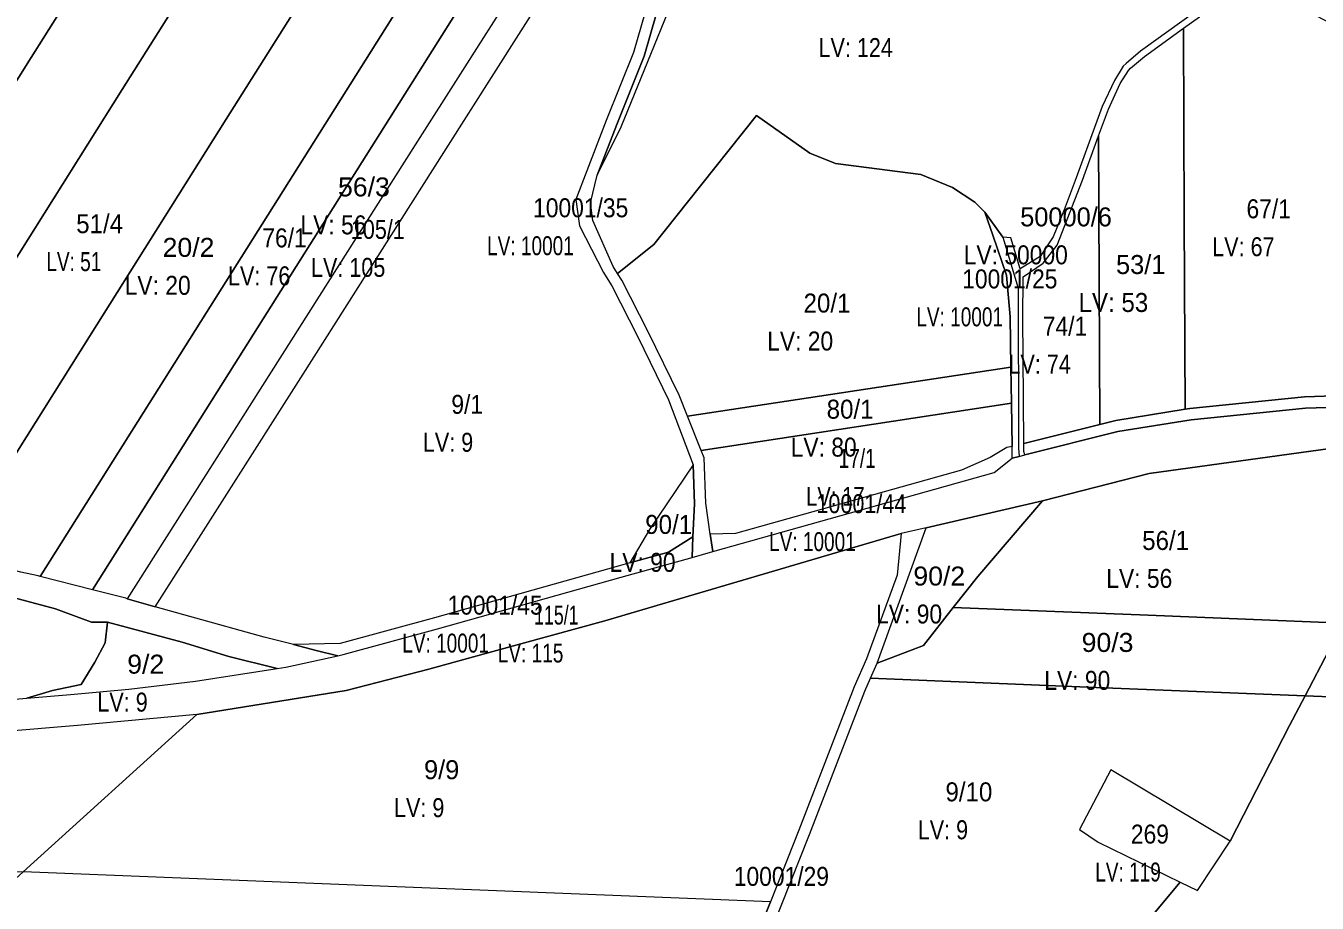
# Model space of a CAD drawing. Extents: x -713758 to -711119, y -1123067 to -1120789.
# Drawn here: x -712228 to -711548, y -1121714 to -1121252 of the extents above; entities that cross this region are included whole.
import ezdxf
from ezdxf.enums import TextEntityAlignment as Align

# ---------------------------------------------------------------- set-up
doc = ezdxf.new("R2010")
doc.units = 0
doc.header["$LTSCALE"] = 4
doc.layers.add('10', color=7, linetype='Continuous', lineweight=13)
doc.layers.add('11', color=7, linetype='Continuous')
doc.layers.add('13', color=7, linetype='Continuous')

msp = doc.modelspace()

# ---------------------------------------------------------------- linework, layer by layer
at = {"layer": '10'}
for points in [[(-712423.44, -1121490.64), (-712347.85, -1121370.61), (-712272.26, -1121250.57), (-712196.67, -1121130.54), (-712185, -1121136.71), (-712169.32, -1121143.39), (-712151.71, -1121151.12), (-712225.62, -1121268.49), (-712299.53, -1121385.85), (-712373.44, -1121503.22), (-712411.12, -1121493.7)], [(-712373.44, -1121503.22), (-712299.53, -1121385.85), (-712225.62, -1121268.49), (-712151.71, -1121151.12), (-712121.32, -1121164.46), (-712105.15, -1121170.27), (-712177.71, -1121285.5), (-712250.27, -1121400.74), (-712322.84, -1121515.97), (-712342.53, -1121511.25), (-712369.84, -1121504.13)], [(-712322.84, -1121515.97), (-712250.27, -1121400.74), (-712177.71, -1121285.5), (-712105.15, -1121170.27), (-712076.52, -1121180.56), (-712064.5, -1121183.42), (-712050.6, -1121186.42), (-712122.79, -1121301.06), (-712194.99, -1121415.7), (-712267.18, -1121530.34), (-712312.23, -1121518.51)], [(-711927.19, -1121330.54), (-711914.62, -1121305.06), (-711890.03, -1121244.84), (-711869.08, -1121184.54), (-711877.22, -1121181.83), (-711901.86, -1121183.16), (-711916.62, -1121185.66), (-711913.13, -1121194.47), (-711902.89, -1121203.34), (-711894.77, -1121216.03), (-711893.42, -1121230.17), (-711896.16, -1121245.95), (-711902.41, -1121267.94), (-711916.98, -1121303.92)], [(-712267.18, -1121530.34), (-712194.99, -1121415.7), (-712122.79, -1121301.06), (-712050.6, -1121186.42), (-712045.54, -1121187.51), (-712026.93, -1121189.41), (-712000.06, -1121191.51), (-712073.66, -1121308.39), (-712147.26, -1121425.26), (-712220.86, -1121542.14), (-712221.92, -1121541.87), (-712231.21, -1121539.78)], [(-712220.86, -1121542.14), (-712147.26, -1121425.26), (-712073.66, -1121308.39), (-712000.06, -1121191.51), (-711991.96, -1121192.14), (-711969.33, -1121193.53), (-712043.98, -1121312.07), (-712118.64, -1121430.62), (-712193.29, -1121549.17)], [(-712193.29, -1121549.17), (-712118.64, -1121430.62), (-712043.98, -1121312.07), (-711969.33, -1121193.53), (-711947.16, -1121194.88), (-712023.15, -1121314.53), (-712099.14, -1121434.18), (-712175.12, -1121553.83), (-712175.81, -1121553.63)], [(-712175.12, -1121553.83), (-712160.23, -1121558.04), (-712083.56, -1121437.33), (-712006.9, -1121316.63), (-711930.24, -1121195.92), (-711947.16, -1121194.88), (-712023.15, -1121314.53), (-712099.14, -1121434.18)], [(-711618.17, -1121253.17), (-711609.76, -1121247.05), (-711603.45, -1121237.97), (-711602.78, -1121237.53), (-711594.67, -1121232.25), (-711577.63, -1121234.79), (-711563.68, -1121238.26), (-711544.69, -1121248.43), (-711525.27, -1121257.57), (-711523.81, -1121258.22), (-711523.01, -1121446.38), (-711554.24, -1121447.4), (-711614.82, -1121453.59), (-711617.32, -1121453.99), (-711617.74, -1121353.58)], [(-711662.88, -1121309.79), (-711657.75, -1121295.8), (-711651.46, -1121282.29), (-711647.11, -1121275.38), (-711646.02, -1121274.27), (-711638.61, -1121268.05), (-711618.17, -1121253.17), (-711617.74, -1121353.58), (-711617.32, -1121453.99), (-711653.87, -1121459.84), (-711662.24, -1121461.94)], [(-711916.53, -1121382.42), (-711897.38, -1121367.21), (-711879.72, -1121344.83), (-711843.34, -1121299.08), (-711815.1, -1121319.03), (-711801.61, -1121324.49), (-711756.69, -1121330.16), (-711739.96, -1121337.15), (-711728.17, -1121344.84), (-711722.83, -1121350.06), (-711718.64, -1121362.29), (-711711.51, -1121383.25), (-711709.53, -1121405.21), (-711709.15, -1121431.75), (-711879.64, -1121457.61), (-711884.11, -1121446.52), (-711900.43, -1121413.1), (-711914.27, -1121385.94)], [(-711702.78, -1121406.41), (-711702.63, -1121384.21), (-711692.16, -1121376.91), (-711684.76, -1121367.47), (-711671.45, -1121333.16), (-711662.88, -1121309.79), (-711662.24, -1121461.94), (-711702.26, -1121471.99), (-711702.67, -1121425.96)], [(-711722.83, -1121350.06), (-711713.32, -1121363.32), (-711705.36, -1121390.09), (-711705.36, -1121405.64), (-711705.06, -1121455.16), (-711705.15, -1121474.49), (-711704.85, -1121478.82), (-711708.45, -1121479.72), (-711708.54, -1121473.56), (-711708.87, -1121450.84), (-711709.15, -1121431.75), (-711709.53, -1121405.21), (-711711.51, -1121383.25), (-711718.64, -1121362.29)], [(-711879.64, -1121457.61), (-711709.15, -1121431.75), (-711708.87, -1121450.84), (-711872.37, -1121475.64)], [(-711872.37, -1121475.64), (-711708.87, -1121450.84), (-711708.54, -1121473.56), (-711711.19, -1121474.22), (-711719.98, -1121479.48), (-711735.24, -1121486.02), (-711854.28, -1121519.39), (-711867.64, -1121519.88), (-711870.02, -1121503.4), (-711870.8, -1121479.52)], [(-711867.64, -1121519.88), (-711866.32, -1121529), (-711717.95, -1121487.4), (-711708.45, -1121479.72), (-711708.54, -1121473.56), (-711711.19, -1121474.22), (-711719.98, -1121479.48), (-711735.24, -1121486.02), (-711854.28, -1121519.39)], [(-711739.48, -1121558.47), (-711726.6, -1121542.17), (-711692.52, -1121502.18), (-711636.21, -1121487.78), (-711535.72, -1121473.88), (-711490.84, -1121475.25), (-711507.4, -1121513.57), (-711534.18, -1121566.68), (-711636.83, -1121562.58)], [(-711910.02, -1121535.02), (-711889.72, -1121529.33), (-711876.74, -1121521.16), (-711876.01, -1121503.92), (-711876.68, -1121483.2), (-711899.75, -1121517.45)], [(-711779.66, -1121587.75), (-711761.86, -1121538.83), (-711753.72, -1121516.45), (-711692.52, -1121502.18), (-711726.6, -1121542.17), (-711739.48, -1121558.47), (-711755.26, -1121578.43)], [(-712229.88, -1121697.85), (-712138.38, -1121614.8), (-712059.59, -1121602.17), (-712016.1, -1121591.07), (-711982.28, -1121581.75), (-711923.15, -1121565.46), (-711766.99, -1121519.55), (-711769.17, -1121541.36), (-711785.23, -1121585.51), (-711791.73, -1121600.27), (-711820.89, -1121675.91), (-711835.92, -1121713.6), (-712032.9, -1121705.73)], [(-712087.41, -1121578.03), (-712075.42, -1121581.12), (-712063.93, -1121583.89), (-712061.14, -1121583.28), (-712011.52, -1121569.7), (-711914.59, -1121542.53), (-711877.21, -1121532.05), (-711876.74, -1121521.16), (-711889.72, -1121529.33), (-711910.02, -1121535.02), (-711916.2, -1121536.75), (-712013.08, -1121563.91), (-712062.72, -1121577.49)], [(-711783.2, -1121595.79), (-711779.66, -1121587.75), (-711755.26, -1121578.43), (-711739.48, -1121558.47), (-711636.83, -1121562.58), (-711534.18, -1121566.68), (-711541.43, -1121581.06), (-711553.99, -1121604.99), (-711668.6, -1121600.39)], [(-712228.02, -1121606.32), (-712204.87, -1121604.37), (-712174.24, -1121601.59), (-712139, -1121597.34), (-712095.99, -1121590.61), (-712121.43, -1121584.31), (-712146.04, -1121576.83), (-712185.46, -1121566.18), (-712186.71, -1121577.16), (-712192.08, -1121587.24), (-712199.33, -1121599.14), (-712214.41, -1121602.18)], [(-711553.99, -1121604.99), (-711541.43, -1121581.06), (-711534.18, -1121566.68), (-711412.4, -1121571.55), (-711290.62, -1121576.42), (-711308.45, -1121614.84), (-711431.22, -1121609.91)], [(-711835.08, -1121727.68), (-711815.31, -1121678.11), (-711786.19, -1121602.57), (-711783.2, -1121595.79), (-711668.6, -1121600.39), (-711553.99, -1121604.99), (-711562.27, -1121620.75), (-711593.45, -1121681.64), (-711656.45, -1121644), (-711672.97, -1121675.46), (-711663.14, -1121682.15), (-711619.93, -1121703.21), (-711643.78, -1121731.83), (-711646.68, -1121735.31)], [(-711646.68, -1121735.31), (-711643.78, -1121731.83), (-711619.93, -1121703.21), (-711610.76, -1121707.68), (-711593.45, -1121681.64), (-711562.27, -1121620.75), (-711553.99, -1121604.99), (-711431.22, -1121609.91), (-711308.45, -1121614.84), (-711315.94, -1121630.99), (-711342.08, -1121687.09), (-711372.92, -1121746.38), (-711509.8, -1121740.84)], [(-712310.25, -1121694.64), (-712229.88, -1121697.85), (-712138.38, -1121614.8), (-712201.33, -1121620.73), (-712241.17, -1121624.1), (-712284.89, -1121666.46)], [(-711672.97, -1121675.46), (-711663.14, -1121682.15), (-711619.93, -1121703.21), (-711610.76, -1121707.68), (-711593.45, -1121681.64), (-711656.45, -1121644)], [(-712345.4, -1121802.72), (-712182.69, -1121809.23), (-712019.97, -1121815.74), (-711857.26, -1121822.25), (-711854.58, -1121793.79), (-711851.16, -1121773.83), (-711848.33, -1121765.03), (-711850.53, -1121760.95), (-711852.87, -1121751.59), (-711845.69, -1121738.11), (-711835.92, -1121713.6), (-712032.9, -1121705.73), (-712229.88, -1121697.85)]]:
    msp.add_lwpolyline(points, close=True, dxfattribs=at)
for points in [[(-711902.02, -1121244.62), (-711908.09, -1121265.99), (-711922.57, -1121301.74), (-711932.79, -1121328.39), (-711938.51, -1121343.33), (-711936.63, -1121357.22), (-711923.91, -1121381.87), (-711921.62, -1121385.61), (-711919.48, -1121388.93), (-711905.79, -1121415.8), (-711889.59, -1121448.96), (-711876.68, -1121483.2), (-711899.75, -1121517.45), (-711910.02, -1121535.02), (-711916.2, -1121536.75), (-712013.08, -1121563.91), (-712062.72, -1121577.49), (-712087.41, -1121578.03), (-712102.81, -1121574.07), (-712142, -1121563.2), (-712160.23, -1121558.04), (-712083.56, -1121437.33), (-712006.9, -1121316.63), (-711930.24, -1121195.92)], [(-711902.02, -1121244.62), (-711908.09, -1121265.99), (-711922.57, -1121301.74), (-711932.79, -1121328.39), (-711938.51, -1121343.33), (-711936.63, -1121357.22), (-711923.91, -1121381.87), (-711921.62, -1121385.61), (-711919.48, -1121388.93), (-711905.79, -1121415.8), (-711889.59, -1121448.96), (-711876.68, -1121483.2), (-711876.01, -1121503.92), (-711876.74, -1121521.16), (-711877.21, -1121532.05), (-711866.32, -1121529), (-711867.64, -1121519.88), (-711870.02, -1121503.4), (-711870.8, -1121479.52), (-711872.37, -1121475.64), (-711879.64, -1121457.61), (-711884.11, -1121446.52), (-711900.43, -1121413.1), (-711914.27, -1121385.94), (-711916.53, -1121382.42), (-711918.75, -1121378.8), (-711929.6, -1121354.46), (-711930.79, -1121345.2), (-711927.19, -1121330.54), (-711916.98, -1121303.92), (-711902.41, -1121267.94), (-711896.16, -1121245.95)], [(-711612.21, -1121244.74), (-711640.77, -1121265.29), (-711648.41, -1121271.7), (-711649.88, -1121273.2), (-711654.53, -1121280.61), (-711660.99, -1121294.46), (-711674.73, -1121331.94), (-711681.08, -1121348.85), (-711686.92, -1121363.09), (-711693.72, -1121373.51), (-711704.16, -1121379.94), (-711709.15, -1121363.61), (-711713.32, -1121363.32), (-711722.83, -1121350.06), (-711728.17, -1121344.84), (-711739.96, -1121337.15), (-711756.69, -1121330.16), (-711801.61, -1121324.49), (-711815.1, -1121319.03), (-711843.34, -1121299.08), (-711879.72, -1121344.83), (-711897.38, -1121367.21), (-711916.53, -1121382.42), (-711918.75, -1121378.8), (-711929.6, -1121354.46), (-711930.79, -1121345.2), (-711927.19, -1121330.54), (-711914.62, -1121305.06), (-711890.03, -1121244.84)], [(-711612.21, -1121244.74), (-711640.77, -1121265.29), (-711648.41, -1121271.7), (-711649.88, -1121273.2), (-711654.53, -1121280.61), (-711660.99, -1121294.46), (-711674.73, -1121331.94), (-711681.08, -1121348.85), (-711686.92, -1121363.09), (-711693.72, -1121373.51), (-711704.16, -1121379.94), (-711709.15, -1121363.61), (-711713.32, -1121363.32), (-711705.36, -1121390.09), (-711705.36, -1121405.64), (-711705.06, -1121455.16), (-711705.15, -1121474.49), (-711704.85, -1121478.82), (-711701.81, -1121478.06), (-711702.22, -1121476.25), (-711702.26, -1121471.99), (-711702.67, -1121425.96), (-711702.78, -1121406.41), (-711702.63, -1121384.21), (-711692.16, -1121376.91), (-711684.76, -1121367.47), (-711671.45, -1121333.16), (-711662.88, -1121309.79), (-711657.75, -1121295.8), (-711651.46, -1121282.29), (-711647.11, -1121275.38), (-711646.02, -1121274.27), (-711638.61, -1121268.05), (-711618.17, -1121253.17), (-711609.76, -1121247.05)], [(-711520.14, -1121452.29), (-711553.84, -1121453.39), (-711614.04, -1121459.54), (-711652.67, -1121465.72), (-711701.81, -1121478.06), (-711702.22, -1121476.25), (-711702.26, -1121471.99), (-711662.24, -1121461.94), (-711653.87, -1121459.84), (-711617.32, -1121453.99), (-711614.82, -1121453.59), (-711554.24, -1121447.4), (-711523.01, -1121446.38)], [(-712372.57, -1121618.47), (-712228.02, -1121606.32), (-712204.87, -1121604.37), (-712174.24, -1121601.59), (-712139, -1121597.34), (-712095.99, -1121590.61), (-712091.36, -1121589.89), (-712063.93, -1121583.89), (-712061.14, -1121583.28), (-712011.52, -1121569.7), (-711914.59, -1121542.53), (-711877.21, -1121532.05), (-711866.32, -1121529), (-711717.95, -1121487.4), (-711708.45, -1121479.72), (-711704.85, -1121478.82), (-711701.81, -1121478.06), (-711652.67, -1121465.72), (-711614.04, -1121459.54), (-711553.84, -1121453.39), (-711520.14, -1121452.29)], [(-711535.72, -1121473.88), (-711636.21, -1121487.78), (-711692.52, -1121502.18), (-711753.72, -1121516.45), (-711766.99, -1121519.55), (-711923.15, -1121565.46), (-711982.28, -1121581.75), (-712016.1, -1121591.07), (-712059.59, -1121602.17), (-712138.38, -1121614.8), (-712201.33, -1121620.73), (-712241.17, -1121624.1)], [(-711835.08, -1121727.68), (-711815.31, -1121678.11), (-711786.19, -1121602.57), (-711783.2, -1121595.79), (-711779.66, -1121587.75), (-711761.86, -1121538.83), (-711753.72, -1121516.45), (-711766.99, -1121519.55), (-711769.17, -1121541.36), (-711785.23, -1121585.51), (-711791.73, -1121600.27), (-711820.89, -1121675.91), (-711835.92, -1121713.6), (-711845.69, -1121738.11)], [(-712243.26, -1121551.08), (-712212.92, -1121559.2), (-712193.87, -1121566.24), (-712185.46, -1121566.18), (-712146.04, -1121576.83), (-712121.43, -1121584.31), (-712095.99, -1121590.61), (-712091.36, -1121589.89), (-712063.93, -1121583.89), (-712075.42, -1121581.12), (-712087.41, -1121578.03), (-712102.81, -1121574.07), (-712142, -1121563.2), (-712160.23, -1121558.04), (-712175.12, -1121553.83), (-712175.81, -1121553.63), (-712193.29, -1121549.17), (-712220.86, -1121542.14), (-712221.92, -1121541.87), (-712231.21, -1121539.78)], [(-712372.57, -1121618.47), (-712228.02, -1121606.32), (-712214.41, -1121602.18), (-712199.33, -1121599.14), (-712192.08, -1121587.24), (-712186.71, -1121577.16), (-712185.46, -1121566.18), (-712193.87, -1121566.24), (-712212.92, -1121559.2), (-712243.26, -1121551.08)]]:
    msp.add_lwpolyline(points, dxfattribs=at)

# ---------------------------------------------------------------- texts
at = {"layer": '11'}
for s, width, p in [('56/3', 1.05, (-712050.24, -1121341.79)), ('10001/35', 0.9, (-711935.951, -1121352.78)), ('67/1', 0.9, (-711573.19, -1121353.31)), ('51/4', 0.95, (-712189.58, -1121361.16)), ('105/1', 0.85, (-712042.91, -1121364.18)), ('76/1', 0.9, (-712092.11, -1121368.66)), ('20/2', 1.05, (-712142.721, -1121373.66)), ('10001/25', 0.9, (-711709.699, -1121390.27)), ('20/1', 0.95, (-711806.08, -1121403.01)), ('74/1', 0.9, (-711680.61, -1121415.22)), ('9/1', 0.9, (-711995.78, -1121456.39)), ('80/1', 0.95, (-711793.9, -1121458.94)), ('17/1', 0.75, (-711790.15, -1121484.88)), ('10001/44', 0.85, (-711787.961, -1121508.75)), ('90/1', 0.95, (-711889.549, -1121519.69)), ('56/1', 0.95, (-711627.55, -1121528.15)), ('90/2', 1.05, (-711746.89, -1121546.9)), ('10001/45', 0.9, (-711981.11, -1121562.24)), ('115/1', 0.7, (-711948.791, -1121567.47)), ('90/3', 1.05, (-711658.16, -1121581.9)), ('9/2', 1.05, (-712165.28, -1121593.35)), ('9/10', 0.95, (-711731.27, -1121660.65)), ('269', 0.9, (-711635.829, -1121682.92)), ('10001/29', 0.9, (-711830.13, -1121705.21))]:
    msp.add_text(s, height=10, dxfattribs=dict(at, width=width)).set_placement(p, align=Align.CENTER)
for s, p in [('50000/6', (-711680.05, -1121357.58)), ('53/1', (-711640.669, -1121382.69)), ('9/9', (-712009.25, -1121648.98))]:
    msp.add_text(s, height=10, dxfattribs=at).set_placement(p, align=Align.CENTER)
at = {"layer": '13'}
for s, width, p in [('LV: 124 ', 0.85, (-711789.374, -1121268.33)), ('LV: 56 ', 0.9, (-712064.628, -1121361.79)), ('LV: 10001 ', 0.75, (-711961.046, -1121372.78)), ('LV: 50000 ', 0.9, (-711704.878, -1121377.58)), ('LV: 67 ', 0.85, (-711584.968, -1121373.31)), ('LV: 51 ', 0.75, (-712201.793, -1121381.16)), ('LV: 105 ', 0.85, (-712056.965, -1121384.18)), ('LV: 76 ', 0.85, (-712103.889, -1121388.66)), ('LV: 20 ', 0.9, (-712157.31, -1121393.66)), ('LV: 53 ', 0.95, (-711653.318, -1121402.69)), ('LV: 10001 ', 0.75, (-711734.728, -1121410.27)), ('LV: 20 ', 0.9, (-711818.561, -1121423.01)), ('LV: 74 ', 0.85, (-711692.389, -1121435.22)), ('LV: 9 ', 0.85, (-712004.312, -1121476.39)), ('LV: 80 ', 0.9, (-711806.147, -1121478.94)), ('LV: 17 ', 0.8, (-711800.188, -1121504.88)), ('LV: 10001 ', 0.75, (-711812.386, -1121528.75)), ('LV: 90 ', 0.9, (-711901.662, -1121539.69)), ('LV: 56 ', 0.9, (-711639.763, -1121548.15)), ('LV: 90 ', 0.9, (-711761.111, -1121566.9)), ('LV: 10001 ', 0.75, (-712005.77, -1121582.24)), ('LV: 115 ', 0.75, (-711960.971, -1121587.47)), ('LV: 90 ', 0.9, (-711672.449, -1121601.9)), ('LV: 9 ', 0.85, (-712175.92, -1121613.35)), ('LV: 9 ', 0.85, (-712019.522, -1121668.98)), ('LV: 9 ', 0.85, (-711743.382, -1121680.65)), ('LV: 119 ', 0.75, (-711645.968, -1121702.92))]:
    msp.add_text(s, height=10, dxfattribs=dict(at, width=width)).set_placement(p, align=Align.CENTER)

doc.saveas('drawing.dxf')
